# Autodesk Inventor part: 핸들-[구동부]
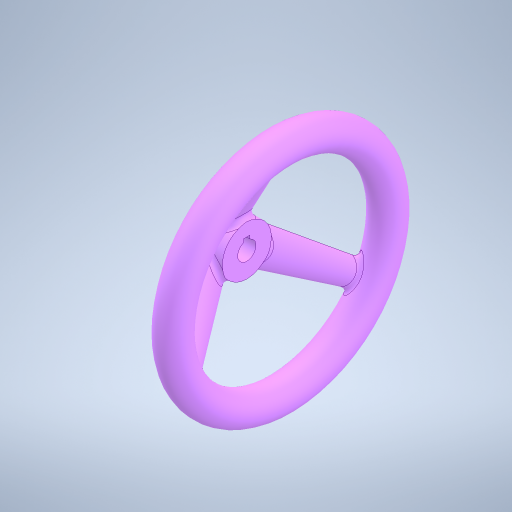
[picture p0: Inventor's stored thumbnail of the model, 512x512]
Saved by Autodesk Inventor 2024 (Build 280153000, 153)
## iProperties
Created: 2024-08
Part Number: 핸들-[구동부]
Material: 강철, 연강
Document SubType Name: Modeling
Designer: user
Density: 7.85 g/cm^3
Appearance: 반연마
Mass: 1364.7 g
Surface Area: 381.092 cm^2
Volume: 173.847 cm^3
Sending System: Autodesk Inventor 2025
Preprocessor: ST-DEVELOPER v20
Author: jhkim
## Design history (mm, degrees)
feature "솔리드1"
node "솔리드2"
